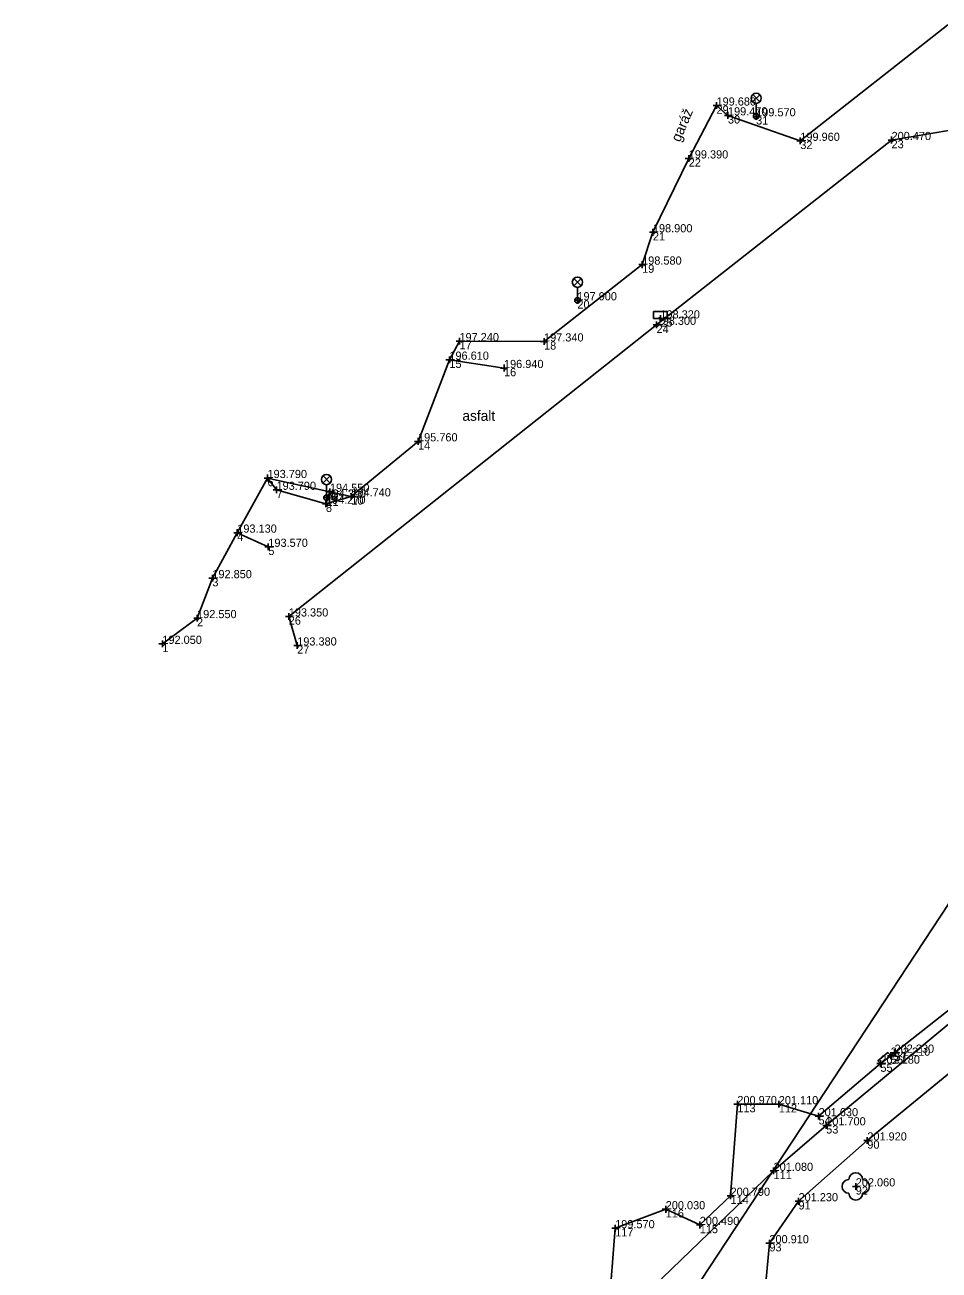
# Model space of a CAD drawing. Extents: x -744883 to -744469, y -966832 to -966374.
# Drawn here: x -744784.2 to -744717.1, y -966471.6 to -966380.2 of the extents above; entities that cross this region are included whole.
import ezdxf

# ---------------------------------------------------------------- set-up
doc = ezdxf.new("R2010")
doc.units = 0
for name, color, linetype in [('Body - výška', 7, 'Continuous'), ('Body - značka', 7, 'Continuous'), ('Body - číslo', 7, 'Continuous'), ('Body polohopisu', 7, 'Continuous'), ('Budovy', 7, 'Continuous'), ('Doplňkové značky', 7, 'Continuous'), ('Ploty_opěrné zdi', 7, 'Continuous'), ('Popisy objektů_povrchů', 7, 'Continuous'), ('Rozhraní ploch', 7, 'Continuous'), ('Stromy_porost', 7, 'Continuous'), ('Vrstva 132', 7, 'Continuous'), ('Vstup na pozemek', 7, 'Continuous'), ('Výšky bodů', 7, 'Continuous'), ('Značky IS', 7, 'Continuous'), ('Čísla bodů', 7, 'Continuous')]:
    doc.layers.add(name, color=color, linetype=linetype)

msp = doc.modelspace()

# ---------------------------------------------------------------- linework, layer by layer
at = {"layer": 'Body - značka'}
for q in [(-744737.77, -966401.77), (-744737.52, -966401.52), (-744737.27, -966401.77), (-744737.52, -966402.02)]:
    msp.add_line((-744737.52, -966401.77), q, dxfattribs=at)
at = {"layer": 'Body polohopisu'}
for p, q in [((-744733.4, -966386.15), (-744733.65, -966386.15)), ((-744733.4, -966386.15), (-744733.4, -966385.9)), ((-744733.4, -966386.15), (-744733.15, -966386.15)), ((-744733.4, -966386.15), (-744733.4, -966386.4)), ((-744732.56, -966386.87), (-744732.81, -966386.87)), ((-744732.56, -966386.87), (-744732.56, -966386.62)), ((-744732.56, -966386.87), (-744732.31, -966386.87)), ((-744732.56, -966386.87), (-744732.56, -966387.12)), ((-744730.49, -966386.94), (-744730.74, -966386.94)), ((-744730.49, -966386.94), (-744730.49, -966386.69)), ((-744730.49, -966386.94), (-744730.24, -966386.94)), ((-744730.49, -966386.94), (-744730.49, -966387.19)), ((-744727.25, -966388.74), (-744727.5, -966388.74)), ((-744727.25, -966388.74), (-744727.25, -966388.49)), ((-744727.25, -966388.74), (-744727, -966388.74)), ((-744727.25, -966388.74), (-744727.25, -966388.99)), ((-744720.55, -966388.68), (-744720.8, -966388.68)), ((-744720.55, -966388.68), (-744720.55, -966388.43)), ((-744720.55, -966388.68), (-744720.3, -966388.68)), ((-744720.55, -966388.68), (-744720.55, -966388.93)), ((-744735.44, -966390.03), (-744735.44, -966389.78)), ((-744735.44, -966390.03), (-744735.69, -966390.03)), ((-744735.44, -966390.03), (-744735.19, -966390.03)), ((-744735.44, -966390.03), (-744735.44, -966390.28)), ((-744738.07, -966395.45), (-744738.07, -966395.2)), ((-744738.07, -966395.45), (-744738.32, -966395.45)), ((-744738.07, -966395.45), (-744737.82, -966395.45)), ((-744738.07, -966395.45), (-744738.07, -966395.7)), ((-744738.86, -966397.82), (-744739.11, -966397.82)), ((-744738.86, -966397.82), (-744738.86, -966397.57)), ((-744738.86, -966397.82), (-744738.61, -966397.82)), ((-744738.86, -966397.82), (-744738.86, -966398.07)), ((-744743.61, -966400.44), (-744743.86, -966400.44)), ((-744743.61, -966400.44), (-744743.61, -966400.19)), ((-744743.61, -966400.44), (-744743.36, -966400.44)), ((-744743.61, -966400.44), (-744743.61, -966400.69)), ((-744737.8, -966402.24), (-744738.05, -966402.24)), ((-744737.8, -966402.24), (-744737.8, -966401.99)), ((-744737.8, -966402.24), (-744737.55, -966402.24)), ((-744737.8, -966402.24), (-744737.8, -966402.49)), ((-744752.27, -966403.44), (-744752.52, -966403.44)), ((-744752.27, -966403.44), (-744752.27, -966403.19)), ((-744752.27, -966403.44), (-744752.02, -966403.44)), ((-744752.27, -966403.44), (-744752.27, -966403.69)), ((-744746.06, -966403.46), (-744746.31, -966403.46)), ((-744746.06, -966403.46), (-744746.06, -966403.21)), ((-744746.06, -966403.46), (-744745.81, -966403.46)), ((-744746.06, -966403.46), (-744746.06, -966403.71)), ((-744753.01, -966404.8), (-744753.26, -966404.8)), ((-744753.01, -966404.8), (-744753.01, -966404.55)), ((-744753.01, -966404.8), (-744752.76, -966404.8)), ((-744753.01, -966404.8), (-744753.01, -966405.05)), ((-744749, -966405.41), (-744749.25, -966405.41)), ((-744749, -966405.41), (-744749, -966405.16)), ((-744749, -966405.41), (-744748.75, -966405.41)), ((-744749, -966405.41), (-744749, -966405.66)), ((-744755.31, -966410.79), (-744755.56, -966410.79)), ((-744755.31, -966410.79), (-744755.31, -966410.54)), ((-744755.31, -966410.79), (-744755.06, -966410.79)), ((-744755.31, -966410.79), (-744755.31, -966411.04)), ((-744766.36, -966413.48), (-744766.61, -966413.48)), ((-744766.36, -966413.48), (-744766.36, -966413.23)), ((-744766.36, -966413.48), (-744766.11, -966413.48)), ((-744766.36, -966413.48), (-744766.36, -966413.73)), ((-744765.7, -966414.35), (-744765.95, -966414.35)), ((-744765.7, -966414.35), (-744765.7, -966414.1)), ((-744765.7, -966414.35), (-744765.45, -966414.35)), ((-744765.7, -966414.35), (-744765.7, -966414.6)), ((-744761.78, -966414.49), (-744762.03, -966414.49)), ((-744761.78, -966414.49), (-744761.78, -966414.24)), ((-744761.78, -966414.49), (-744761.53, -966414.49)), ((-744761.78, -966414.49), (-744761.78, -966414.74)), ((-744760.21, -966414.83), (-744760.21, -966414.58)), ((-744762.07, -966415.37), (-744762.32, -966415.37)), ((-744762.03, -966414.92), (-744762.28, -966414.92)), ((-744762.07, -966415.37), (-744762.07, -966415.12)), ((-744762.07, -966415.37), (-744761.82, -966415.37)), ((-744762.07, -966415.37), (-744762.07, -966415.62)), ((-744762.03, -966414.92), (-744762.03, -966414.67)), ((-744762.03, -966414.92), (-744761.78, -966414.92)), ((-744762.03, -966414.92), (-744762.03, -966415.17)), ((-744760.21, -966414.83), (-744760.46, -966414.83)), ((-744760.21, -966414.83), (-744759.96, -966414.83)), ((-744760.21, -966414.83), (-744760.21, -966415.08)), ((-744768.58, -966417.49), (-744768.58, -966417.24)), ((-744768.58, -966417.49), (-744768.83, -966417.49)), ((-744768.58, -966417.49), (-744768.33, -966417.49)), ((-744768.58, -966417.49), (-744768.58, -966417.74)), ((-744766.3, -966418.53), (-744766.55, -966418.53)), ((-744766.3, -966418.53), (-744766.3, -966418.28)), ((-744766.3, -966418.53), (-744766.05, -966418.53)), ((-744766.3, -966418.53), (-744766.3, -966418.78)), ((-744770.41, -966420.83), (-744770.66, -966420.83)), ((-744770.41, -966420.83), (-744770.41, -966420.58)), ((-744770.41, -966420.83), (-744770.16, -966420.83)), ((-744770.41, -966420.83), (-744770.41, -966421.08)), ((-744771.53, -966423.76), (-744771.53, -966423.51)), ((-744764.8, -966423.64), (-744765.05, -966423.64)), ((-744764.8, -966423.64), (-744764.8, -966423.39)), ((-744764.8, -966423.64), (-744764.55, -966423.64)), ((-744764.8, -966423.64), (-744764.8, -966423.89)), ((-744771.53, -966423.76), (-744771.78, -966423.76)), ((-744771.53, -966423.76), (-744771.28, -966423.76)), ((-744771.53, -966423.76), (-744771.53, -966424.01)), ((-744774.08, -966425.65), (-744774.08, -966425.4)), ((-744764.18, -966425.77), (-744764.18, -966425.52)), ((-744774.08, -966425.65), (-744774.33, -966425.65)), ((-744774.08, -966425.65), (-744773.83, -966425.65)), ((-744774.08, -966425.65), (-744774.08, -966425.9)), ((-744764.18, -966425.77), (-744764.43, -966425.77)), ((-744764.18, -966425.77), (-744763.93, -966425.77)), ((-744764.18, -966425.77), (-744764.18, -966426.02)), ((-744720.61, -966455.87), (-744720.61, -966455.62)), ((-744720.33, -966455.65), (-744720.58, -966455.65)), ((-744720.33, -966455.65), (-744720.33, -966455.4)), ((-744720.33, -966455.65), (-744720.08, -966455.65)), ((-744720.33, -966455.65), (-744720.33, -966455.9)), ((-744721.37, -966456.45), (-744721.62, -966456.45)), ((-744721.37, -966456.45), (-744721.37, -966456.2)), ((-744721.37, -966456.45), (-744721.12, -966456.45)), ((-744721.37, -966456.45), (-744721.37, -966456.7)), ((-744720.61, -966455.87), (-744720.86, -966455.87)), ((-744720.61, -966455.87), (-744720.36, -966455.87)), ((-744720.61, -966455.87), (-744720.61, -966456.12)), ((-744731.87, -966459.42), (-744731.87, -966459.17)), ((-744728.83, -966459.43), (-744728.83, -966459.18)), ((-744731.87, -966459.42), (-744732.12, -966459.42)), ((-744731.87, -966459.42), (-744731.62, -966459.42)), ((-744731.87, -966459.42), (-744731.87, -966459.67)), ((-744728.83, -966459.43), (-744729.08, -966459.43)), ((-744728.83, -966459.43), (-744728.58, -966459.43)), ((-744728.83, -966459.43), (-744728.83, -966459.68)), ((-744725.91, -966460.31), (-744725.91, -966460.06)), ((-744725.91, -966460.31), (-744726.16, -966460.31)), ((-744725.91, -966460.31), (-744725.66, -966460.31)), ((-744725.91, -966460.31), (-744725.91, -966460.56)), ((-744725.35, -966460.98), (-744725.6, -966460.98)), ((-744725.35, -966460.98), (-744725.35, -966460.73)), ((-744725.35, -966460.98), (-744725.1, -966460.98)), ((-744725.35, -966460.98), (-744725.35, -966461.23)), ((-744722.33, -966462.09), (-744722.58, -966462.09)), ((-744722.33, -966462.09), (-744722.33, -966461.84)), ((-744722.33, -966462.09), (-744722.08, -966462.09)), ((-744722.33, -966462.09), (-744722.33, -966462.34)), ((-744729.21, -966464.32), (-744729.46, -966464.32)), ((-744729.21, -966464.32), (-744729.21, -966464.07)), ((-744729.21, -966464.32), (-744728.96, -966464.32)), ((-744729.21, -966464.32), (-744729.21, -966464.57)), ((-744723.18, -966465.46), (-744723.43, -966465.46)), ((-744723.18, -966465.46), (-744723.18, -966465.21)), ((-744723.18, -966465.46), (-744722.93, -966465.46)), ((-744723.18, -966465.46), (-744723.18, -966465.71)), ((-744732.37, -966466.15), (-744732.62, -966466.15)), ((-744732.37, -966466.15), (-744732.37, -966465.9)), ((-744732.37, -966466.15), (-744732.12, -966466.15)), ((-744732.37, -966466.15), (-744732.37, -966466.4)), ((-744727.38, -966466.55), (-744727.63, -966466.55)), ((-744727.38, -966466.55), (-744727.38, -966466.3)), ((-744727.38, -966466.55), (-744727.13, -966466.55)), ((-744727.38, -966466.55), (-744727.38, -966466.8)), ((-744737.13, -966467.14), (-744737.38, -966467.14)), ((-744737.13, -966467.14), (-744737.13, -966466.89)), ((-744737.13, -966467.14), (-744736.88, -966467.14)), ((-744737.13, -966467.14), (-744737.13, -966467.39)), ((-744740.84, -966468.53), (-744740.84, -966468.28)), ((-744734.63, -966468.29), (-744734.88, -966468.29)), ((-744734.63, -966468.29), (-744734.63, -966468.04)), ((-744734.63, -966468.29), (-744734.38, -966468.29)), ((-744734.63, -966468.29), (-744734.63, -966468.54)), ((-744740.84, -966468.53), (-744741.09, -966468.53)), ((-744740.84, -966468.53), (-744740.59, -966468.53)), ((-744740.84, -966468.53), (-744740.84, -966468.78)), ((-744729.52, -966469.63), (-744729.52, -966469.38)), ((-744729.52, -966469.63), (-744729.77, -966469.63)), ((-744729.52, -966469.63), (-744729.27, -966469.63)), ((-744729.52, -966469.63), (-744729.52, -966469.88))]:
    msp.add_line(p, q, dxfattribs=at)
at = {"layer": 'Budovy'}
msp.add_lwpolyline([(-744733.4, -966386.15), (-744735.44, -966390.03)], dxfattribs=at)
at = {"layer": 'Doplňkové značky'}
for p, q in [((-744730.754, -966385.878), (-744730.226, -966385.35)), ((-744730.218, -966385.875), (-744730.746, -966385.346)), ((-744730.49, -966385.99), (-744730.49, -966386.74)), ((-744743.874, -966399.378), (-744743.346, -966398.85)), ((-744743.338, -966399.375), (-744743.866, -966398.846)), ((-744743.61, -966399.49), (-744743.61, -966400.24)), ((-744762.294, -966413.858), (-744761.766, -966413.33)), ((-744761.758, -966413.855), (-744762.286, -966413.326)), ((-744762.03, -966413.97), (-744762.03, -966414.72))]:
    msp.add_line(p, q, dxfattribs=at)
for centre, radius in [((-744730.49, -966385.615), 0.375), ((-744730.49, -966386.94), 0.2), ((-744743.61, -966399.115), 0.375), ((-744743.61, -966400.44), 0.2), ((-744762.03, -966413.595), 0.375), ((-744762.03, -966414.92), 0.2)]:
    msp.add_circle(centre, radius, dxfattribs=at)
at = {"layer": 'Ploty_opěrné zdi'}
for points in [[(-744733.4, -966386.15), (-744732.56, -966386.87), (-744727.25, -966388.74), (-744716.41, -966380.23)], [(-744710.87, -966400.94), (-744709.95, -966395.38), (-744712.15, -966389.52), (-744714.79, -966387.7), (-744720.55, -966388.68)], [(-744720.55, -966388.68), (-744737.8, -966402.24), (-744764.8, -966423.64), (-744764.18, -966425.77)], [(-744752.27, -966403.44), (-744746.06, -966403.46), (-744738.86, -966397.82), (-744738.07, -966395.45)], [(-744760.21, -966414.83), (-744755.31, -966410.79), (-744753.01, -966404.8)], [(-744753.01, -966404.8), (-744749, -966405.41)], [(-744766.36, -966413.48), (-744761.78, -966414.49), (-744760.21, -966414.83)], [(-744768.58, -966417.49), (-744766.3, -966418.53)], [(-744774.08, -966425.65), (-744771.53, -966423.76), (-744770.41, -966420.83)], [(-744720.61, -966455.87), (-744720.33, -966455.65), (-744709.69, -966447.28), (-744706.75, -966444.87), (-744700.21, -966438.43), (-744698.32, -966435.86), (-744697.77, -966432.84), (-744697.98, -966429.55)], [(-744728.83, -966459.43), (-744725.91, -966460.31), (-744721.37, -966456.45)], [(-744731.87, -966459.42), (-744732.37, -966466.15), (-744734.63, -966468.29), (-744737.13, -966467.14)], [(-744740.84, -966468.53), (-744741.3, -966474.5), (-744749.45, -966482.01), (-744750.2, -966482.69)]]:
    msp.add_lwpolyline(points, dxfattribs=at)
at = {"layer": 'Rozhraní ploch'}
for points in [[(-744656.79, -966394.28), (-744668.08, -966407.88), (-744687.08, -966429.58), (-744696.8, -966440.03), (-744704.1, -966447.15), (-744722.33, -966462.09), (-744727.38, -966466.55), (-744729.52, -966469.63), (-744729.89, -966473.57)], [(-744766.36, -966413.48), (-744765.7, -966414.35), (-744762.07, -966415.37), (-744761.78, -966414.49), (-744760.21, -966414.83)], [(-744760.21, -966414.83), (-744762.07, -966415.37)], [(-744700.21, -966438.43), (-744705.49, -966444.43), (-744711.93, -966449.89), (-744725.35, -966460.98), (-744729.21, -966464.32), (-744740.73, -966475.43), (-744748.38, -966483.65), (-744749.45, -966482.01)]]:
    msp.add_lwpolyline(points, dxfattribs=at)
at = {"layer": 'Stromy_porost'}
msp.add_circle((-744723.18, -966465.46), 0.0005, dxfattribs=at)
for centre, start, end in [((-744723.18, -966464.96), 0, 179.99999), ((-744723.68, -966465.46), 89.99999, 269.99999), ((-744722.68, -966465.46), 270, 89.99999), ((-744723.18, -966465.96), 179.99999, 359.99999)]:
    msp.add_arc(centre, 0.5, start, end, dxfattribs=at)
at = {"layer": 'Vrstva 132'}
msp.add_lwpolyline([(-744784.17, -966607.48), (-744776.1, -966571.48), (-744766.46, -966535.83), (-744760.61, -966514.26), (-744741.19, -966482.43), (-744714.51, -966441.91), (-744696.14, -966413.51)], dxfattribs=at)
at = {"layer": 'Vstup na pozemek'}
for points in [[(-744738.07, -966395.45), (-744735.44, -966390.03)], [(-744753.01, -966404.8), (-744752.27, -966403.44)], [(-744770.41, -966420.83), (-744768.58, -966417.49), (-744766.36, -966413.48)], [(-744728.83, -966459.43), (-744731.87, -966459.42)], [(-744737.13, -966467.14), (-744740.84, -966468.53)]]:
    msp.add_lwpolyline(points, dxfattribs=at)
at = {"layer": 'Značky IS'}
msp.add_lwpolyline([(-744738.02, -966401.77), (-744738.02, -966401.27), (-744737.02, -966401.27), (-744737.02, -966401.77)], close=True, dxfattribs=at)
msp.add_lwpolyline([(-744720.61, -966455.87), (-744720.817, -966455.645), (-744721.553, -966456.242), (-744721.37, -966456.45), (-744720.61, -966455.87)], dxfattribs=at)

# ---------------------------------------------------------------- texts
at = {"layer": 'Body - výška'}
msp.add_text('198.320', height=0.6, dxfattribs=at).set_placement((-744737.52, -966401.77))
at = {"layer": 'Body - číslo'}
msp.add_text('25', height=0.6, dxfattribs=at).set_placement((-744737.52, -966402.37))
at = {"layer": 'Popisy objektů_povrchů'}
msp.add_text('garáž', height=0.75, rotation=67.10042, dxfattribs=at).set_placement((-744736.083, -966388.871))
for s, p in [('asfalt', (-744752.052, -966409.28)), ('b.', (-744761.71, -966415.11))]:
    msp.add_text(s, height=0.75, dxfattribs=at).set_placement(p)
at = {"layer": 'Výšky bodů'}
for s, p in [('199.680', (-744733.4, -966386.15)), ('199.470', (-744732.56, -966386.87)), ('199.570', (-744730.49, -966386.94)), ('200.470', (-744720.55, -966388.68)), ('199.960', (-744727.25, -966388.74)), ('199.390', (-744735.44, -966390.03)), ('198.900', (-744738.07, -966395.45)), ('198.580', (-744738.86, -966397.82)), ('197.900', (-744743.61, -966400.44)), ('198.300', (-744737.8, -966402.24)), ('197.240', (-744752.27, -966403.44)), ('197.340', (-744746.06, -966403.46)), ('196.610', (-744753.01, -966404.8)), ('196.940', (-744749, -966405.41)), ('195.760', (-744755.31, -966410.79)), ('193.790', (-744766.36, -966413.48)), ('193.790', (-744765.7, -966414.35)), ('194.390', (-744762.03, -966414.92)), ('194.550', (-744761.78, -966414.49)), ('194.740', (-744760.21, -966414.83)), ('194.270', (-744762.07, -966415.37)), ('193.130', (-744768.58, -966417.49)), ('193.570', (-744766.3, -966418.53)), ('192.850', (-744770.41, -966420.83)), ('192.550', (-744771.53, -966423.76)), ('193.350', (-744764.8, -966423.64)), ('192.050', (-744774.08, -966425.65)), ('193.380', (-744764.18, -966425.77)), ('202.210', (-744720.61, -966455.87)), ('202.230', (-744720.33, -966455.65)), ('202.180', (-744721.37, -966456.45)), ('200.970', (-744731.87, -966459.42)), ('201.110', (-744728.83, -966459.43)), ('201.630', (-744725.91, -966460.31)), ('201.700', (-744725.35, -966460.98)), ('201.920', (-744722.33, -966462.09)), ('201.080', (-744729.21, -966464.32)), ('200.790', (-744732.37, -966466.15)), ('202.060', (-744723.18, -966465.46)), ('200.030', (-744737.13, -966467.14)), ('201.230', (-744727.38, -966466.55)), ('199.570', (-744740.84, -966468.53)), ('200.490', (-744734.63, -966468.29)), ('200.910', (-744729.52, -966469.63))]:
    msp.add_text(s, height=0.6, dxfattribs=at).set_placement(p)
at = {"layer": 'Čísla bodů'}
for s, p in [('29', (-744733.4, -966386.75)), ('30', (-744732.56, -966387.47)), ('31', (-744730.49, -966387.54)), ('32', (-744727.25, -966389.34)), ('23', (-744720.55, -966389.28)), ('22', (-744735.44, -966390.63)), ('21', (-744738.07, -966396.05)), ('19', (-744738.86, -966398.42)), ('20', (-744743.61, -966401.04)), ('24', (-744737.8, -966402.84)), ('17', (-744752.27, -966404.04)), ('18', (-744746.06, -966404.06)), ('15', (-744753.01, -966405.4)), ('16', (-744749, -966406.01)), ('14', (-744755.31, -966411.39)), ('6', (-744766.36, -966414.08)), ('7', (-744765.7, -966414.95)), ('9', (-744761.78, -966415.09)), ('8', (-744762.07, -966415.97)), ('11', (-744762.03, -966415.52)), ('10', (-744760.21, -966415.43)), ('4', (-744768.58, -966418.09)), ('5', (-744766.3, -966419.13)), ('3', (-744770.41, -966421.43)), ('26', (-744764.8, -966424.24)), ('2', (-744771.53, -966424.36)), ('1', (-744774.08, -966426.25)), ('27', (-744764.18, -966426.37)), ('57', (-744720.33, -966456.25)), ('55', (-744721.37, -966457.05)), ('56', (-744720.61, -966456.47)), ('113', (-744731.87, -966460.02)), ('112', (-744728.83, -966460.03)), ('54', (-744725.91, -966460.91)), ('53', (-744725.35, -966461.58)), ('90', (-744722.33, -966462.69)), ('111', (-744729.21, -966464.92)), ('92', (-744723.18, -966466.06)), ('114', (-744732.37, -966466.75)), ('91', (-744727.38, -966467.15)), ('116', (-744737.13, -966467.74)), ('115', (-744734.63, -966468.89)), ('117', (-744740.84, -966469.13)), ('93', (-744729.52, -966470.23))]:
    msp.add_text(s, height=0.6, dxfattribs=at).set_placement(p)

doc.saveas('drawing.dxf')
